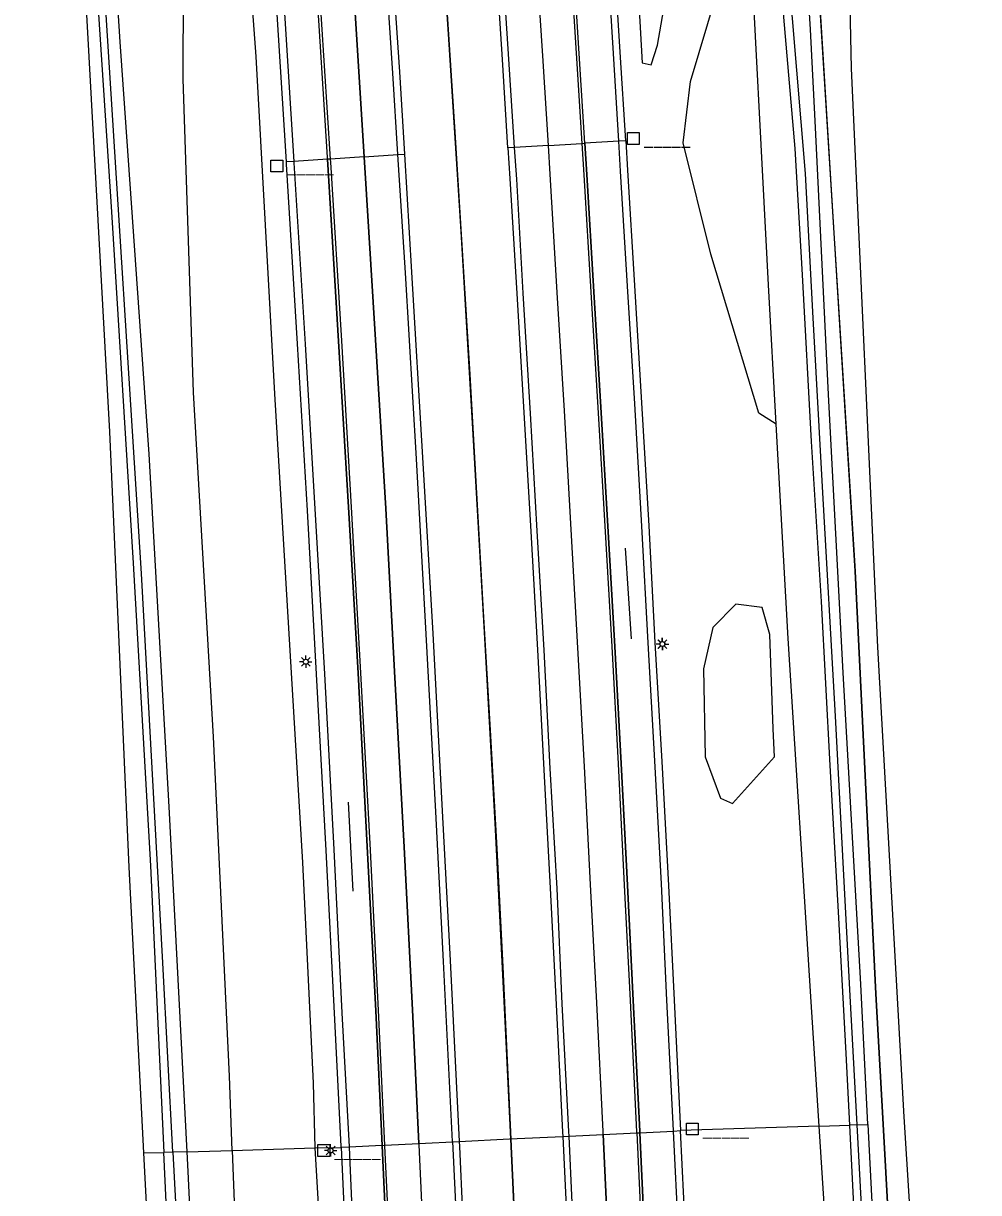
# Model space of a CAD drawing. Extents: x 133000 to 136000, y 400500 to 403500.
# Drawn here: x 133091.9 to 133188.4, y 402050.2 to 402168.4 of the extents above; entities that cross this region are included whole.
import ezdxf

# ---------------------------------------------------------------- set-up
doc = ezdxf.new("R2010")
doc.units = 0
for name, color, linetype in [('gg-afsc-muur', 7, 'Continuous'), ('gg-knt-bronhoudergrens', 7, 'Continuous'), ('gg-kntw-beschoeiing', 7, 'Continuous'), ('gt-knt-geleideconstructie', 7, 'Continuous'), ('gt-symb-hm paal', 7, 'Continuous'), ('gt-symb-lichtmast', 7, 'Continuous'), ('gx-grn-maaiveld', 7, 'Continuous'), ('gx-knt-lijn weginrichtingselement', 7, 'Continuous')]:
    doc.layers.add(name, color=color, linetype=linetype)

# ---------------------------------------------------------------- blocks, each defined once
blk = doc.blocks.new('gt0-HMpaal')
at = {"layer": 'gt-symb-hm paal'}
blk.add_lwpolyline([(-0.6, 0.6), (0.6, 0.6), (0.6, -0.6), (-0.6, -0.6)], close=True, dxfattribs=at)
blk = doc.blocks.new('gt0-LMAST')
at = {"layer": 'gt-symb-lichtmast'}
for p, q in [((-0.18, 0.17), (-0.45, 0.44)), ((-0.01, 0.25), (-0.01, 0.62)), ((0.17, 0.17), (0.44, 0.44)), ((-0.26, 0), (-0.63, 0)), ((-0.18, -0.18), (-0.45, -0.45)), ((-0.01, -0.25), (-0.01, -0.63)), ((0.44, -0.45), (0.17, -0.18)), ((0.24, 0), (0.62, 0))]:
    blk.add_line(p, q, dxfattribs=at)
blk.add_circle((-0.01, 0), 0.25, dxfattribs=at)

msp = doc.modelspace()

# ---------------------------------------------------------------- linework, layer by layer
at = {"layer": 'gg-afsc-muur'}
msp.add_lwpolyline([(133175.88, 402112.99), (133174.35, 402137.91), (133170.15, 402206.25)], dxfattribs=at)
at = {"layer": 'gg-knt-bronhoudergrens'}
msp.add_lwpolyline([(133227.07, 402236.71), (133190.98, 402213.36), (133187.46, 402210.75), (133183.84, 402207.08), (133181.74, 402204.5), (133180.17, 402202.57), (133178.13, 402198.29), (133176.65, 402193.81), (133175.35, 402189.26), (133175.07, 402184.51), (133175.49, 402163.81), (133178.14, 402105.34), (133180.81, 402057.85), (133183.58, 402013.99), (133184.64, 401997.19)], dxfattribs=at)
at = {"layer": 'gg-kntw-beschoeiing'}
msp.add_lwpolyline([(133181.09, 402012.37), (133180.14, 402031.49), (133178.71, 402057.13), (133177.97, 402070.28), (133175.88, 402112.99)], dxfattribs=at)
at = {"layer": 'gt-knt-geleideconstructie'}
msp.add_lwpolyline([(133144.94, 401965.09), (133144.48, 401977.08), (133144.05, 401989.08), (133143.54, 402001.06), (133143.07, 402013.07), (133142.58, 402025.07), (133142.05, 402037.06), (133141.45, 402049.05), (133140.33, 402073.01), (133139.72, 402084.96), (133139.05, 402096.95), (133138.36, 402108.92), (133137.66, 402120.88), (133137, 402132.88), (133135.53, 402156.86), (133134.76, 402168.8), (133133.95, 402180.77), (133133.15, 402192.73), (133132.61, 402200.98)], dxfattribs=at)
at = {"layer": 'gx-grn-maaiveld'}
for p, q in [((133172.26, 402056.92), (133158.24, 402056.46)), ((133172.26, 402056.92), (133175.36, 402057.02)), ((133176.05, 402057.04), (133175.36, 402057.02)), ((133176.05, 402057.04), (133177.19, 402057.08)), ((133131.81, 402055.15), (133135.9, 402055.36)), ((133104.01, 402054.21), (133106.04, 402054.26)), ((133106.96, 402054.29), (133106.04, 402054.26)), ((133108.36, 402054.33), (133106.96, 402054.29)), ((133108.36, 402054.33), (133112.96, 402054.45)), ((133112.96, 402054.45), (133121.3, 402054.73)), ((133121.3, 402054.73), (133123.98, 402054.76))]:
    msp.add_line(p, q, dxfattribs=at)
for points in [[(133080.56, 402388.5), (133080.6, 402389.67), (133081.07, 402390.63), (133081.72, 402391.07), (133082.64, 402391.32), (133083.66, 402391.38), (133084.49, 402391.32), (133084.83, 402391.04), (133085.25, 402390.39), (133087.28, 402363.52), (133088.54, 402348.98), (133090.73, 402323.7), (133092.85, 402297.8), (133093.48, 402290.14), (133094.74, 402269.49), (133096.08, 402250.89), (133097.48, 402231.95), (133099.38, 402201.38), (133101.6, 402166.51), (133104.54, 402124.82), (133106.54, 402089.18), (133108.36, 402054.33)], [(133175.36, 402057.02), (133175, 402064.25), (133174.21, 402078.59), (133173.38, 402093.36), (133172.51, 402109.93), (133171.48, 402126.12), (133170.56, 402142.96), (133169.84, 402155.74), (133168.69, 402169.01), (133167.5, 402184.3), (133166.4, 402199.05), (133165.41, 402215.74), (133164.4, 402232.57), (133163.33, 402245.77), (133162.17, 402257.71), (133161.02, 402269.87), (133159.85, 402282.02), (133158.84, 402299.05)], [(133090.59, 402297.7), (133092.42, 402274.04), (133095.35, 402231.83), (133100.76, 402149.32), (133102.95, 402113.83), (133104.7, 402083.24), (133106.04, 402054.26)], [(133112.96, 402054.45), (133112.67, 402061.96), (133111.06, 402096.27), (133109.05, 402131.05), (133108, 402162.77), (133108.05, 402171.93), (133107.56, 402192.92), (133107.04, 402219.64), (133107.92, 402232.34), (133106.45, 402263.93), (133104.77, 402297.21), (133107.82, 402263.03), (133110.68, 402228.11), (133115.36, 402165.02), (133117.22, 402130.94), (133120.05, 402083.56), (133121.13, 402061.27), (133121.3, 402054.73)], [(133160.04, 402294.08), (133162.33, 402264.67), (133163.74, 402249.84), (133164.16, 402244.15), (133164.56, 402238.46), (133165.14, 402231.94), (133165.83, 402221.01), (133166.78, 402205.98), (133167.78, 402189.8), (133170.84, 402153.2), (133171.57, 402139.22), (133172.57, 402121.53), (133173.88, 402098.34), (133175.35, 402070.1), (133176.05, 402057.04)], [(133106.96, 402054.29), (133105.95, 402073.41), (133103.8, 402112.78), (133100.18, 402169.76), (133097.86, 402206.24), (133096.04, 402230.93), (133094.93, 402248.75), (133093.35, 402269.9), (133091.9, 402287.86)], [(133092.54, 402261.03), (133093.4, 402251.12), (133095.45, 402213.7), (133098.01, 402173.57), (133100.57, 402127.1), (133102.52, 402083.08), (133104.01, 402054.21)], [(133148.59, 402156.25), (133148.02, 402165.32), (133147.26, 402177.13), (133146.53, 402187.75), (133145.54, 402202.41), (133144.6, 402215.99), (133143.6, 402230.25), (133142.54, 402244.5), (133141.63, 402256.21)], [(133152.72, 402156.49), (133152.14, 402165.47), (133151.44, 402176.88), (133150.7, 402188.08), (133149.68, 402202.65), (133148.77, 402215.97), (133147.68, 402230.75), (133146.62, 402244.93), (133145.73, 402256.52)], [(133140.81, 402155.79), (133140.25, 402164.72), (133139.48, 402176.68), (133138.95, 402184.72), (133138.18, 402195.6), (133137.32, 402208.18), (133136.34, 402222.07), (133135.32, 402235.78), (133134.29, 402249.49), (133133.83, 402255.61)], [(133144.91, 402156.03), (133144.35, 402165.08), (133143.57, 402176.85), (133142.85, 402187.43), (133141.86, 402202.12), (133140.92, 402215.7), (133139.93, 402229.89), (133138.87, 402244.29), (133137.97, 402255.93)], [(133118.43, 402154.37), (133117.22, 402173.6), (133116.17, 402189.65), (133114.79, 402209.42), (133113.5, 402226.89), (133112.27, 402243.59), (133111.48, 402253.86)], [(133122.6, 402154.64), (133122.59, 402154.86), (133121.4, 402173.49), (133120.28, 402190.05), (133118.96, 402209.55), (133117.65, 402227.37), (133116.43, 402243.7), (133115.61, 402254.2)], [(133126.28, 402154.89), (133126.25, 402155.4), (133125.12, 402173.78), (133123.99, 402190.51), (133122.65, 402209.67), (133121.36, 402227.47), (133120.15, 402243.86), (133119.33, 402254.51)], [(133123.38, 402254.84), (133123.65, 402251.45), (133124.98, 402233.99), (133126.26, 402216.7), (133127.51, 402199.02), (133128.62, 402181.78), (133129.85, 402163.46), (133130.35, 402155.16)], [(133177.19, 402057.08), (133176.48, 402071.26), (133174.69, 402102.73), (133173.2, 402130.86), (133171.85, 402158.52), (133171.39, 402167.75), (133170.76, 402178.13), (133168.39, 402205.53), (133168.35, 402206.14)], [(133170.15, 402206.25), (133171.13, 402189.1), (133173.81, 402146.13), (133175.88, 402112.99), (133177.97, 402070.28), (133178.71, 402057.13), (133180.14, 402031.49), (133181.09, 402012.37)], [(133155.92, 402166.16), (133158.99, 402183.75), (133158.73, 402184.46), (133154.01, 402189.62), (133153.23, 402189.51), (133153, 402188.86), (133154.39, 402164.37), (133155.27, 402164.18), (133155.92, 402166.16)], [(133167.92, 402127.85), (133166.18, 402128.99), (133161.33, 402145.04), (133158.53, 402156.28), (133159.26, 402162.49), (133163.64, 402177.17), (133165.1, 402181.25)], [(133167.92, 402127.85), (133167.14, 402141.93), (133165.1, 402181.25)], [(133144.91, 402156.03), (133141.49, 402155.83), (133140.81, 402155.79)], [(133140.81, 402155.79), (133141.01, 402152.7), (133141.71, 402141.06), (133142.42, 402129.03), (133143.12, 402117), (133143.79, 402105.05), (133144.43, 402092.93), (133145.07, 402080.96), (133145.7, 402069.2), (133146.33, 402056.3), (133146.35, 402055.86)], [(133144.91, 402156.03), (133148.28, 402156.23), (133148.59, 402156.25)], [(133150.44, 402056.07), (133150.43, 402056.37), (133149.79, 402069.37), (133149.16, 402081.35), (133148.56, 402093.27), (133147.89, 402105.24), (133147.21, 402117.22), (133146.52, 402129.22), (133145.8, 402141.18), (133145.09, 402153.14), (133144.91, 402156.03)], [(133152.72, 402156.49), (133152.01, 402156.45), (133148.59, 402156.25)], [(133148.59, 402156.25), (133148.79, 402153.08), (133149.51, 402141.23), (133150.19, 402129.57), (133150.91, 402117.57), (133151.61, 402105.4), (133152.27, 402093.55), (133152.88, 402081.26), (133153.48, 402069.62), (133154.13, 402056.41), (133154.14, 402056.25)], [(133152.72, 402156.49), (133152.91, 402153.55), (133153.61, 402141.89), (133154.31, 402130.03), (133155.06, 402117.59), (133155.67, 402105.78), (133156.36, 402093.78), (133157.03, 402081.24), (133157.61, 402069.64), (133158.24, 402056.49), (133158.24, 402056.46)], [(133122.6, 402154.64), (133119.18, 402154.42), (133118.43, 402154.37)], [(133126.28, 402154.89), (133122.9, 402154.66), (133122.6, 402154.64)], [(133122.6, 402154.64), (133123.7, 402136.24), (133124.72, 402119.48), (133125.68, 402102.71), (133126.6, 402085.18), (133127.46, 402068.57), (133128.1, 402054.96)], [(133126.28, 402154.89), (133129.7, 402155.11), (133130.35, 402155.16)], [(133131.81, 402055.15), (133131.17, 402068.66), (133130.34, 402085.11), (133129.37, 402102.86), (133128.47, 402119.33), (133127.42, 402136.39), (133126.28, 402154.89)], [(133130.35, 402155.16), (133131.08, 402143.24), (133132.2, 402124.49), (133133.22, 402106.72), (133134.18, 402088.78), (133134.97, 402073.65), (133135.9, 402055.36)], [(133123.98, 402054.76), (133123.98, 402054.88), (133123.3, 402068.33), (133122.45, 402084.77), (133121.48, 402102.6), (133120.55, 402119.12), (133119.54, 402135.97), (133118.45, 402154.13), (133118.43, 402154.37)], [(133172.26, 402056.92), (133171.45, 402069.48), (133169.12, 402106.19), (133167.92, 402127.85)], [(133166.49, 402109.33), (133163.84, 402109.68), (133161.53, 402107.32), (133160.57, 402103.13), (133160.73, 402094.24), (133162.29, 402090.07), (133163.52, 402089.54), (133167.75, 402094.23), (133167.62, 402097.08), (133167.28, 402106.61), (133166.49, 402109.33)], [(133154.14, 402056.25), (133157.55, 402056.42), (133158.24, 402056.46)], [(133161.89, 401970.75), (133161.38, 401985.29), (133160.74, 402000.39), (133160.07, 402016.84), (133159.41, 402032.01), (133158.77, 402046.18), (133158.24, 402056.46)], [(133174.56, 402019.19), (133174.2, 402026.52), (133172.26, 402056.92)], [(133176.05, 402057.04), (133177.4, 402032.03), (133178.51, 402008.9), (133179.7, 401989.36), (133180.34, 401940.21), (133181.46, 401906.42), (133181.54, 401901.72), (133182.25, 401857.4), (133183.35, 401809.95), (133183.23, 401809.55), (133183.03, 401809.33), (133182.8, 401809.26), (133182.54, 401809.3), (133182.3, 401809.63), (133181.77, 401846.49), (133180.25, 401901.69), (133180.03, 401909.63), (133178.78, 401979.28), (133178.42, 401989.73), (133177.79, 402004.82), (133177.25, 402019.98), (133176.41, 402036.17), (133175.69, 402050.24), (133175.36, 402057.02)], [(133177.19, 402057.08), (133177.97, 402041.36), (133179.64, 402012.29)], [(133135.9, 402055.36), (133140.96, 402055.63), (133146.35, 402055.86)], [(133135.9, 402055.36), (133135.92, 402054.85), (133136.53, 402041.26), (133137.36, 402023.49), (133138.08, 402006.77), (133138.78, 401989.13), (133139.35, 401973), (133140.01, 401955.51)], [(133146.35, 402055.86), (133146.99, 402055.89), (133150.44, 402056.07)], [(133146.35, 402055.86), (133146.99, 402042.45), (133147.59, 402028.48), (133148.21, 402014.75), (133148.8, 402000.86), (133149.37, 401986.34), (133149.96, 401971.19), (133150.47, 401956.9), (133150.5, 401955.88)], [(133150.44, 402056.07), (133153.83, 402056.24), (133154.14, 402056.25)], [(133150.44, 402056.07), (133150.91, 402045.91), (133151.57, 402031.84), (133152.25, 402016.7), (133152.92, 402000.01), (133153.56, 401984.75), (133154.09, 401970.18), (133154.6, 401956.02)], [(133154.14, 402056.25), (133154.6, 402046.05), (133155.3, 402031.82), (133155.95, 402016.74), (133156.61, 402000.09), (133157.23, 401984.86), (133157.78, 401970.38), (133158.29, 401956.15)], [(133104.01, 402054.21), (133104.44, 402045.88), (133105.84, 402021.64), (133107.24, 401997.39)], [(133110.16, 401960.62), (133109.12, 401993.28), (133108.36, 402006.14), (133106.81, 402037.75), (133106.04, 402054.26)], [(133106.96, 402054.29), (133108.87, 402018.29), (133110.29, 401985.16), (133111.54, 401953.81)], [(133108.36, 402054.33), (133108.47, 402052.32), (133110.21, 402015.35), (133111.65, 401982.46), (133112.86, 401949.88), (133113.88, 401916.23), (133114.47, 401900.41), (133115.39, 401875.3), (133116.4, 401826.4), (133115.7, 401816.24), (133115.91, 401815.75), (133116.72, 401815.32), (133124.58, 401816.32), (133125.02, 401816.02), (133125.2, 401815.5), (133125.11, 401810.46), (133124.98, 401810.09), (133124.48, 401809.89), (133118.92, 401810.42), (133114.13, 401811.62), (133112.8, 401812.75)], [(133112.96, 402054.45), (133114.08, 402025.85), (133117.58, 401989.27), (133117.94, 401974.68), (133119.97, 401948.5), (133119.89, 401942.54), (133118.25, 401927.47), (133116.69, 401907.37), (133118.79, 401900.45), (133119.49, 401898.15), (133122.31, 401893.7), (133123.78, 401889.96), (133123.97, 401883.83), (133125.15, 401850.74), (133126.29, 401824.41), (133126.07, 401808.22), (133125.46, 401807.24)], [(133121.3, 402054.73), (133122.52, 402034.1), (133123.55, 402004.08), (133124.35, 401981.6), (133123.64, 401945.95), (133123.48, 401928.54), (133124.21, 401920.93), (133126.55, 401911.21), (133126.87, 401905.45), (133127.29, 401895.39), (133128.72, 401847.35), (133129.41, 401810.46), (133129.77, 401808.49), (133129.93, 401807.92), (133129.99, 401802.66), (133129.51, 401793.52), (133129.92, 401767.08), (133130.44, 401731.11), (133130.44, 401730.56)], [(133128.1, 402054.96), (133124.76, 402054.8), (133123.98, 402054.76)], [(133123.98, 402054.76), (133124.62, 402040.73), (133125.42, 402023.42), (133126.17, 402006.04), (133126.85, 401988.79), (133127.36, 401973.62)], [(133128.1, 402054.96), (133128.37, 402054.98), (133131.81, 402055.15)], [(133128.1, 402054.96), (133128.1, 402054.92), (133128.74, 402041.05), (133129.57, 402023.28), (133130.27, 402006.49), (133130.99, 401988.98), (133131.6, 401973.02), (133132.2, 401955.24)], [(133131.81, 402055.15), (133131.82, 402055.02), (133132.44, 402041.17), (133133.26, 402023.29), (133133.97, 402006.57), (133134.69, 401989.09), (133135.3, 401973.11), (133135.93, 401955.37)]]:
    msp.add_lwpolyline(points, dxfattribs=at)
at = {"layer": 'gx-knt-lijn weginrichtingselement'}
for p, q in [((133153.3, 402106.15), (133152.71, 402115.33)), ((133124.67, 402089.65), (133125.15, 402080.67))]:
    msp.add_line(p, q, dxfattribs=at)
for points in [[(133144.78, 401967.69), (133144.05, 401987.72), (133143.27, 402007.62), (133142.45, 402027.66), (133141.48, 402047.59), (133141.1, 402055.61), (133140.54, 402067.53), (133139.52, 402087.54), (133138.42, 402107.41), (133137.27, 402127.4), (133136.08, 402147.33), (133134.81, 402167.27), (133133.5, 402187.16), (133132.17, 402207.11), (133130.68, 402226.95), (133129.25, 402246.92), (133127.7, 402266.79), (133126.15, 402286.73), (133124.49, 402306.61)], [(133112.25, 402253.92), (133113.06, 402243.52), (133114.27, 402226.93), (133115.51, 402209.34), (133116.88, 402189.73), (133117.96, 402173.71), (133119.18, 402154.42), (133119.19, 402154.26), (133120.32, 402135.96), (133121.3, 402119.3), (133122.29, 402102.64), (133123.22, 402084.89), (133124.04, 402068.38), (133124.76, 402054.81), (133124.76, 402054.8), (133125.37, 402040.72), (133126.16, 402023.3), (133126.87, 402006.12), (133127.57, 401988.84), (133128.24, 401971.66)], [(133131.6, 401973.02), (133130.99, 401988.98), (133130.27, 402006.49), (133129.57, 402023.28), (133128.74, 402041.05), (133128.1, 402054.92), (133128.1, 402054.96), (133127.46, 402068.57), (133126.6, 402085.18), (133125.68, 402102.71), (133124.72, 402119.48), (133123.7, 402136.24), (133122.6, 402154.64), (133122.59, 402154.86), (133121.4, 402173.49), (133120.28, 402190.05), (133118.96, 402209.55), (133117.65, 402227.37), (133116.43, 402243.7), (133115.61, 402254.2)], [(133131.92, 401973.04), (133131.33, 401989.02), (133130.62, 402006.51), (133129.92, 402023.28), (133129.05, 402041.05), (133128.37, 402054.91), (133128.37, 402054.98), (133127.75, 402068.62), (133126.9, 402085.45), (133125.97, 402102.74), (133125.02, 402119.46), (133124.04, 402136.27), (133122.92, 402154.33), (133122.9, 402154.66), (133121.68, 402173.54), (133120.62, 402190.06), (133119.25, 402209.58), (133117.97, 402227.36), (133116.74, 402243.77), (133115.94, 402254.23)], [(133119.33, 402254.51), (133120.15, 402243.86), (133121.36, 402227.47), (133122.65, 402209.67), (133123.99, 402190.51), (133125.12, 402173.78), (133126.25, 402155.4), (133126.28, 402154.89), (133127.42, 402136.39), (133128.47, 402119.33), (133129.37, 402102.86), (133130.34, 402085.11), (133131.17, 402068.66), (133131.81, 402055.15), (133131.82, 402055.02), (133132.44, 402041.17), (133133.26, 402023.29), (133133.97, 402006.57), (133134.69, 401989.09), (133135.3, 401973.11)], [(133135.23, 402055.37), (133134.31, 402073.56), (133133.53, 402088.68), (133132.56, 402106.63), (133131.59, 402124.37), (133130.46, 402143.17), (133129.7, 402155.11), (133129.18, 402163.34), (133127.98, 402181.72), (133126.83, 402198.99), (133125.54, 402216.62), (133124.32, 402233.82), (133122.99, 402251.46), (133122.73, 402254.79)], [(133146.96, 402177.14), (133147.72, 402165.36), (133148.28, 402156.23), (133148.48, 402153.06), (133149.18, 402141.19), (133149.9, 402129.54), (133150.59, 402117.54), (133151.31, 402105.39), (133151.95, 402093.52), (133152.57, 402081.28), (133153.16, 402069.6), (133153.82, 402056.34), (133153.83, 402056.24), (133154.32, 402046.07), (133154.98, 402031.81), (133155.62, 402016.81), (133156.33, 402000.07), (133156.92, 401984.84), (133157.46, 401970.38)], [(133157.78, 401970.38), (133157.23, 401984.86), (133156.61, 402000.09), (133155.95, 402016.74), (133155.3, 402031.82), (133154.6, 402046.05), (133154.14, 402056.25), (133154.13, 402056.41), (133153.48, 402069.62), (133152.88, 402081.26), (133152.27, 402093.55), (133151.61, 402105.4), (133150.91, 402117.57), (133150.19, 402129.57), (133149.51, 402141.23), (133148.79, 402153.08), (133148.59, 402156.25), (133148.02, 402165.32), (133147.26, 402177.13)], [(133150.6, 401971.13), (133150.02, 401986.33), (133149.43, 402000.85), (133148.86, 402014.76), (133148.27, 402028.43), (133147.62, 402042.43), (133146.99, 402055.89), (133146.97, 402056.37), (133146.3, 402069.26), (133145.78, 402080.92), (133145.09, 402093.05), (133144.46, 402105.03), (133143.78, 402117.08), (133143.08, 402128.94), (133142.37, 402141.09), (133141.7, 402152.62), (133141.49, 402155.83), (133140.92, 402164.74), (133140.12, 402176.68)], [(133154.09, 401970.18), (133153.56, 401984.75), (133152.92, 402000.01), (133152.25, 402016.7), (133151.57, 402031.84), (133150.91, 402045.91), (133150.44, 402056.07), (133150.43, 402056.37), (133149.79, 402069.37), (133149.16, 402081.35), (133148.56, 402093.27), (133147.89, 402105.24), (133147.21, 402117.22), (133146.52, 402129.22), (133145.8, 402141.18), (133145.09, 402153.14), (133144.91, 402156.03), (133144.35, 402165.08), (133143.57, 402176.85)], [(133161.19, 401970.68), (133160.63, 401985.28), (133160.04, 402000.3), (133159.36, 402016.83), (133158.72, 402031.87), (133158.06, 402046.15), (133157.55, 402056.42), (133157.55, 402056.48), (133156.88, 402069.63), (133156.34, 402081.42), (133155.66, 402093.83), (133155, 402105.75), (133154.34, 402117.56), (133153.64, 402129.91), (133152.91, 402141.81), (133152.2, 402153.42), (133152.01, 402156.45), (133151.47, 402165.34), (133150.76, 402176.82)], [(133135.23, 402055.37), (133135.71, 402044.87), (133136.41, 402029.18), (133137.22, 402011.62), (133137.91, 401994.04), (133138.6, 401976.48), (133139.24, 401958.89)]]:
    msp.add_lwpolyline(points, dxfattribs=at)

# ---------------------------------------------------------------- block references
at = {"layer": 'gt-symb-hm paal'}
for p in [(133153.49, 402156.74), (133117.47, 402153.96), (133159.44, 402056.62), (133122.22, 402054.45)]:
    msp.add_blockref('gt0-HMpaal', p, dxfattribs=at)
at = {"layer": 'gt-symb-lichtmast'}
for p in [(133156.42, 402105.64), (133156.44, 402105.64), (133120.4, 402103.85), (133122.91, 402054.46)]:
    msp.add_blockref('gt0-LMAST', p, dxfattribs=at)

# ---------------------------------------------------------------- texts
at = {"layer": 'gt-symb-hm paal'}
for p in [(133154.58, 402156.14), (133118.55, 402153.36), (133160.52, 402056.01), (133123.3, 402053.84)]:
    msp.add_text('_____', height=1.25, dxfattribs=at).set_placement(p)

doc.saveas('drawing.dxf')
